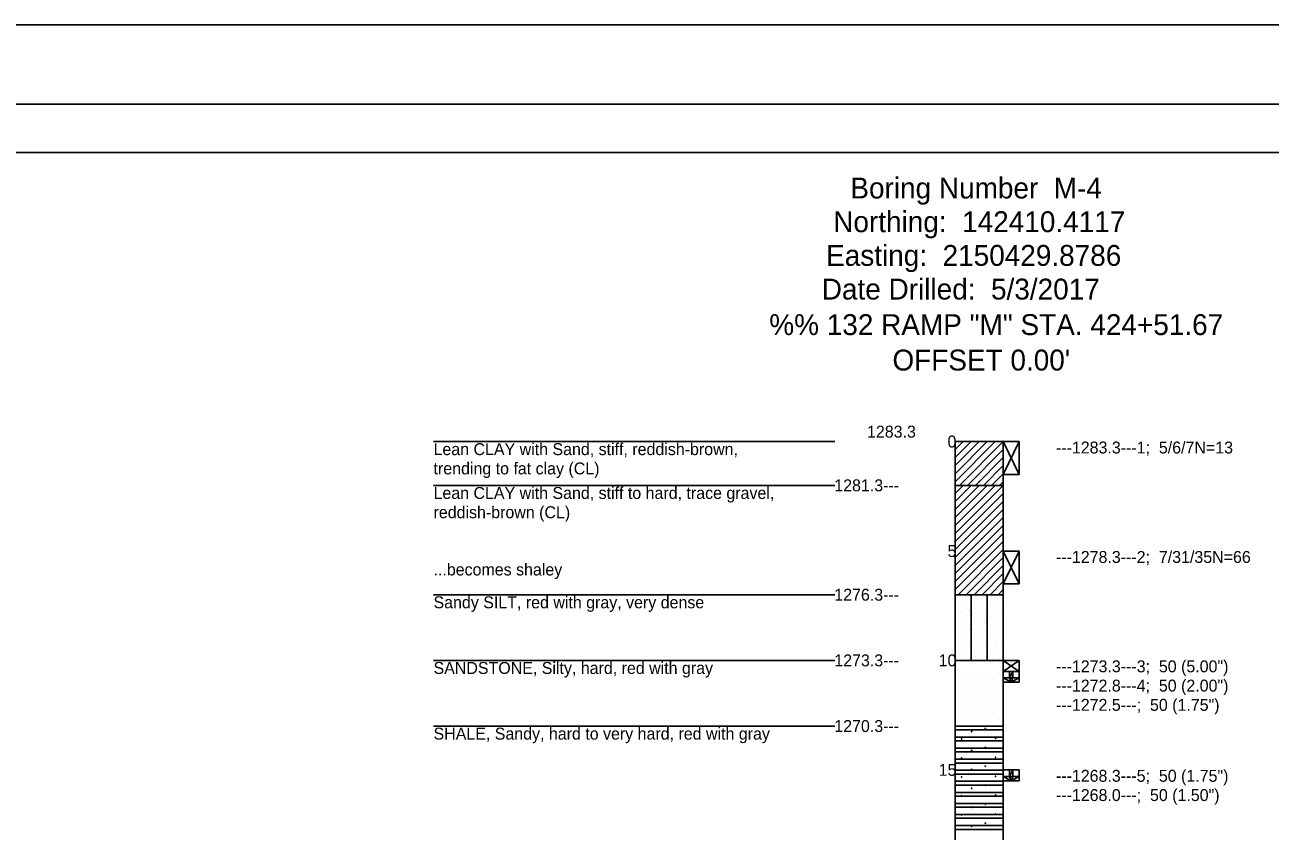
# Model space of a CAD drawing. Extents: x 2150161.5 to 2150203.1, y 143779.5 to 143868.5.
# Drawn here: x 2150182.3 to 2150195.23, y 143825.31 to 143833.69 of the extents above; entities that cross this region are included whole.
import ezdxf

# ---------------------------------------------------------------- set-up
doc = ezdxf.new("R2010")
doc.units = 0
for name, color, linetype in [('Default', 7, 'Continuous'), ('SHT_Plot_Shape_Full', 7, 'Continuous'), ('SHT_Plot_Shape_Half', 7, 'Continuous'), ('SHT_Sheet_Border', 7, 'Continuous')]:
    doc.layers.add(name, color=color, linetype=linetype)

# ---------------------------------------------------------------- blocks, each defined once
blk = doc.blocks.new('POINT_DISPLAY')
at = {"layer": 'Default'}
blk.add_line((0, 0), (0, 0), dxfattribs=at)

msp = doc.modelspace()

# ---------------------------------------------------------------- linework, layer by layer
at = {"layer": 'Default'}
for points in [[(2150186.544, 143829.36), (2150190.71, 143829.36)], [(2150191.96, 143829.276), (2150192.044, 143829.36)], [(2150191.96, 143829.193), (2150192.127, 143829.36)], [(2150191.96, 143829.11), (2150192.21, 143829.36)], [(2150191.96, 143829.026), (2150192.294, 143829.36)], [(2150191.96, 143828.943), (2150192.377, 143829.36)], [(2150191.96, 143829.36), (2150191.96, 143817.2)], [(2150191.96, 143829.36), (2150192.46, 143829.36)], [(2150192.006, 143828.905), (2150192.46, 143829.36)], [(2150192.089, 143828.905), (2150192.46, 143829.276)], [(2150192.46, 143829.36), (2150192.627, 143829.019)], [(2150192.46, 143829.019), (2150192.627, 143829.36)], [(2150192.46, 143829.36), (2150192.627, 143829.36)], [(2150192.46, 143829.36), (2150192.46, 143817.2)], [(2150192.627, 143829.019), (2150192.627, 143829.36)], [(2150192.173, 143828.905), (2150192.46, 143829.193)], [(2150192.256, 143828.905), (2150192.46, 143829.11)], [(2150192.339, 143828.905), (2150192.46, 143829.026)], [(2150192.46, 143829.019), (2150192.627, 143829.019)], [(2150186.544, 143828.905), (2150190.71, 143828.905)], [(2150191.96, 143828.905), (2150192.46, 143828.905)], [(2150191.96, 143828.822), (2150192.044, 143828.905)], [(2150191.96, 143828.738), (2150192.127, 143828.905)], [(2150191.96, 143828.655), (2150192.21, 143828.905)], [(2150191.96, 143828.572), (2150192.294, 143828.905)], [(2150191.96, 143828.488), (2150192.377, 143828.905)], [(2150191.96, 143828.405), (2150192.46, 143828.905)], [(2150192.423, 143828.905), (2150192.46, 143828.943)], [(2150191.96, 143828.322), (2150192.46, 143828.822)], [(2150191.96, 143828.238), (2150192.46, 143828.738)], [(2150191.96, 143828.155), (2150192.46, 143828.655)], [(2150191.96, 143828.072), (2150192.46, 143828.572)], [(2150191.96, 143827.988), (2150192.46, 143828.488)], [(2150191.96, 143827.905), (2150192.46, 143828.405)], [(2150191.96, 143827.822), (2150192.46, 143828.322)], [(2150191.991, 143827.769), (2150192.46, 143828.238)], [(2150192.074, 143827.769), (2150192.46, 143828.155)], [(2150192.46, 143828.223), (2150192.627, 143827.882)], [(2150192.46, 143827.882), (2150192.627, 143828.223)], [(2150192.46, 143828.223), (2150192.627, 143828.223)], [(2150192.627, 143827.882), (2150192.627, 143828.223)], [(2150192.157, 143827.769), (2150192.46, 143828.072)], [(2150192.241, 143827.769), (2150192.46, 143827.988)], [(2150192.324, 143827.769), (2150192.46, 143827.905)], [(2150192.46, 143827.882), (2150192.627, 143827.882)], [(2150186.544, 143827.769), (2150190.71, 143827.769)], [(2150191.96, 143827.769), (2150192.46, 143827.769)], [(2150192.127, 143827.087), (2150192.127, 143827.769)], [(2150192.294, 143827.087), (2150192.294, 143827.769)], [(2150192.407, 143827.769), (2150192.46, 143827.822)], [(2150186.544, 143827.087), (2150190.71, 143827.087)], [(2150191.96, 143827.087), (2150192.46, 143827.087)], [(2150192.46, 143827.087), (2150192.627, 143826.973)], [(2150192.46, 143826.973), (2150192.627, 143827.087)], [(2150192.46, 143827.087), (2150192.627, 143827.087)], [(2150192.627, 143826.973), (2150192.627, 143827.087)], [(2150192.46, 143826.973), (2150192.627, 143826.973)], [(2150192.46, 143826.973), (2150192.627, 143826.973)], [(2150192.627, 143826.86), (2150192.627, 143826.973)], [(2150192.46, 143826.86), (2150192.627, 143826.86)], [(2150186.544, 143826.405), (2150190.71, 143826.405)], [(2150191.96, 143826.405), (2150192.46, 143826.405)], [(2150191.96, 143826.405), (2150192.46, 143826.405)], [(2150191.96, 143826.366), (2150192.46, 143826.366)], [(2150192.135, 143826.349), (2150192.134, 143826.352), (2150192.131, 143826.352), (2150192.129, 143826.349), (2150192.131, 143826.346), (2150192.134, 143826.346), (2150192.135, 143826.349)], [(2150192.278, 143826.381), (2150192.276, 143826.384), (2150192.273, 143826.384), (2150192.272, 143826.381), (2150192.273, 143826.378), (2150192.276, 143826.378), (2150192.278, 143826.381)], [(2150191.96, 143826.29), (2150192.46, 143826.29)], [(2150191.96, 143826.251), (2150192.46, 143826.251)], [(2150191.96, 143826.175), (2150192.46, 143826.175)], [(2150192.031, 143826.27), (2150192.029, 143826.273), (2150192.026, 143826.273), (2150192.024, 143826.27), (2150192.026, 143826.267), (2150192.029, 143826.267), (2150192.031, 143826.27)], [(2150192.278, 143826.184), (2150192.276, 143826.187), (2150192.273, 143826.187), (2150192.272, 143826.184), (2150192.273, 143826.181), (2150192.276, 143826.181), (2150192.278, 143826.184)], [(2150192.384, 143826.277), (2150192.382, 143826.28), (2150192.379, 143826.28), (2150192.377, 143826.277), (2150192.379, 143826.274), (2150192.382, 143826.274), (2150192.384, 143826.277)], [(2150191.96, 143826.136), (2150192.46, 143826.136)], [(2150191.96, 143826.06), (2150192.46, 143826.06)], [(2150192.031, 143826.073), (2150192.029, 143826.076), (2150192.026, 143826.076), (2150192.024, 143826.073), (2150192.026, 143826.07), (2150192.029, 143826.07), (2150192.031, 143826.073)], [(2150192.135, 143826.152), (2150192.134, 143826.155), (2150192.131, 143826.155), (2150192.129, 143826.152), (2150192.131, 143826.149), (2150192.134, 143826.149), (2150192.135, 143826.152)], [(2150192.384, 143826.08), (2150192.382, 143826.083), (2150192.379, 143826.083), (2150192.377, 143826.08), (2150192.379, 143826.077), (2150192.382, 143826.077), (2150192.384, 143826.08)], [(2150191.96, 143826.021), (2150192.46, 143826.021)], [(2150191.96, 143825.946), (2150192.46, 143825.946)], [(2150192.135, 143825.955), (2150192.134, 143825.958), (2150192.131, 143825.958), (2150192.129, 143825.955), (2150192.131, 143825.953), (2150192.134, 143825.953), (2150192.135, 143825.955)], [(2150192.278, 143825.987), (2150192.276, 143825.99), (2150192.273, 143825.99), (2150192.272, 143825.987), (2150192.273, 143825.984), (2150192.276, 143825.984), (2150192.278, 143825.987)], [(2150192.46, 143825.95), (2150192.627, 143825.95)], [(2150192.627, 143825.837), (2150192.627, 143825.95)], [(2150191.96, 143825.906), (2150192.46, 143825.906)], [(2150191.96, 143825.831), (2150192.46, 143825.831)], [(2150191.96, 143825.791), (2150192.46, 143825.791)], [(2150192.031, 143825.876), (2150192.029, 143825.879), (2150192.026, 143825.879), (2150192.024, 143825.876), (2150192.026, 143825.874), (2150192.029, 143825.874), (2150192.031, 143825.876)], [(2150192.278, 143825.79), (2150192.276, 143825.793), (2150192.273, 143825.793), (2150192.272, 143825.79), (2150192.273, 143825.788), (2150192.276, 143825.788), (2150192.278, 143825.79)], [(2150192.384, 143825.883), (2150192.382, 143825.886), (2150192.379, 143825.886), (2150192.377, 143825.883), (2150192.379, 143825.88), (2150192.382, 143825.88), (2150192.384, 143825.883)], [(2150192.46, 143825.837), (2150192.627, 143825.837)], [(2150191.96, 143825.716), (2150192.46, 143825.716)], [(2150191.96, 143825.677), (2150192.46, 143825.677)], [(2150192.031, 143825.68), (2150192.029, 143825.682), (2150192.026, 143825.682), (2150192.024, 143825.68), (2150192.026, 143825.677), (2150192.029, 143825.677), (2150192.031, 143825.68)], [(2150192.135, 143825.759), (2150192.134, 143825.761), (2150192.131, 143825.761), (2150192.129, 143825.759), (2150192.131, 143825.756), (2150192.134, 143825.756), (2150192.135, 143825.759)], [(2150192.384, 143825.686), (2150192.382, 143825.689), (2150192.379, 143825.689), (2150192.377, 143825.686), (2150192.379, 143825.683), (2150192.382, 143825.683), (2150192.384, 143825.686)], [(2150191.96, 143825.601), (2150192.46, 143825.601)], [(2150191.96, 143825.562), (2150192.46, 143825.562)], [(2150192.135, 143825.562), (2150192.134, 143825.565), (2150192.131, 143825.565), (2150192.129, 143825.562), (2150192.131, 143825.559), (2150192.134, 143825.559), (2150192.135, 143825.562)], [(2150192.278, 143825.594), (2150192.276, 143825.596), (2150192.273, 143825.596), (2150192.272, 143825.594), (2150192.273, 143825.591), (2150192.276, 143825.591), (2150192.278, 143825.594)], [(2150191.96, 143825.486), (2150192.46, 143825.486)], [(2150191.96, 143825.447), (2150192.46, 143825.447)], [(2150192.031, 143825.483), (2150192.029, 143825.486), (2150192.026, 143825.486), (2150192.024, 143825.483), (2150192.026, 143825.48), (2150192.029, 143825.48), (2150192.031, 143825.483)], [(2150192.278, 143825.397), (2150192.276, 143825.4), (2150192.273, 143825.4), (2150192.272, 143825.397), (2150192.273, 143825.394), (2150192.276, 143825.394), (2150192.278, 143825.397)], [(2150192.384, 143825.489), (2150192.382, 143825.492), (2150192.379, 143825.492), (2150192.377, 143825.489), (2150192.379, 143825.486), (2150192.382, 143825.486), (2150192.384, 143825.489)], [(2150191.96, 143825.372), (2150192.46, 143825.372)], [(2150191.96, 143825.332), (2150192.46, 143825.332)], [(2150192.135, 143825.365), (2150192.134, 143825.368), (2150192.131, 143825.368), (2150192.129, 143825.365), (2150192.131, 143825.362), (2150192.134, 143825.362), (2150192.135, 143825.365)]]:
    msp.add_lwpolyline(points, dxfattribs=at)
for points in [[(2150192.527, 143826.905), (2150192.56, 143826.905), (2150192.56, 143826.973), (2150192.527, 143826.905)], [(2150192.527, 143826.905), (2150192.56, 143826.973), (2150192.527, 143826.973), (2150192.527, 143826.905)], [(2150192.527, 143826.905), (2150192.46, 143826.905), (2150192.544, 143826.86), (2150192.527, 143826.905)], [(2150192.527, 143826.905), (2150192.544, 143826.86), (2150192.56, 143826.905), (2150192.527, 143826.905)], [(2150192.544, 143826.86), (2150192.627, 143826.905), (2150192.56, 143826.905), (2150192.544, 143826.86)], [(2150192.527, 143825.882), (2150192.56, 143825.882), (2150192.56, 143825.95), (2150192.527, 143825.882)], [(2150192.527, 143825.882), (2150192.56, 143825.95), (2150192.527, 143825.95), (2150192.527, 143825.882)], [(2150192.527, 143825.882), (2150192.46, 143825.882), (2150192.544, 143825.837), (2150192.527, 143825.882)], [(2150192.527, 143825.882), (2150192.544, 143825.837), (2150192.56, 143825.882), (2150192.527, 143825.882)], [(2150192.544, 143825.837), (2150192.627, 143825.882), (2150192.56, 143825.882), (2150192.544, 143825.837)]]:
    msp.add_lwpolyline(points, close=True, dxfattribs=at)
at = {"layer": 'SHT_Plot_Shape_Full'}
msp.add_lwpolyline([(2150164.575, 143833.688), (2150200.575, 143833.688), (2150200.575, 143809.688), (2150164.575, 143809.688)], close=True, dxfattribs=at)
at = {"layer": 'SHT_Plot_Shape_Half'}
msp.add_lwpolyline([(2150166.212, 143832.863), (2150200.212, 143832.863), (2150200.212, 143810.863), (2150166.212, 143810.863)], close=True, dxfattribs=at)
at = {"layer": 'SHT_Sheet_Border'}
msp.add_lwpolyline([(2150199.662, 143811.363), (2150168.162, 143811.363), (2150168.162, 143832.363), (2150199.662, 143832.363)], close=True, dxfattribs=at)

# ---------------------------------------------------------------- block references
at = {"layer": 'Default', "xscale": 0.39369999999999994, "yscale": 0.3936999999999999}
for p in [(2150191.966, 143829.276), (2150192, 143829.343), (2150192.066, 143829.31), (2150192.166, 143829.343), (2150192.189, 143829.279), (2150192.266, 143829.31), (2150192.386, 143829.326), (2150192.433, 143829.276), (2150192, 143829.176), (2150192.033, 143829.243), (2150192.1, 143829.21), (2150192.233, 143829.243), (2150192.25, 143829.167), (2150192.333, 143829.243), (2150192.4, 143829.176), (2150191.966, 143829.043), (2150192.033, 143829.11), (2150192.1, 143829.076), (2150192.166, 143829.143), (2150192.185, 143829.066), (2150192.266, 143829.11), (2150192.384, 143829.091), (2150192.433, 143829.043), (2150192, 143828.888), (2150192.033, 143828.91), (2150192.066, 143829.01), (2150192.133, 143828.976), (2150192.166, 143828.888), (2150192.2, 143828.943), (2150192.236, 143828.996), (2150192.279, 143828.91), (2150192.3, 143829.01), (2150192.366, 143828.976), (2150192.4, 143828.91), (2150191.966, 143828.822), (2150192.033, 143828.788), (2150192.066, 143828.855), (2150192.189, 143828.825), (2150192.233, 143828.788), (2150192.266, 143828.855), (2150192.333, 143828.788), (2150192.386, 143828.872), (2150192.433, 143828.822), (2150192, 143828.722), (2150192.033, 143828.655), (2150192.1, 143828.755), (2150192.166, 143828.688), (2150192.25, 143828.713), (2150192.266, 143828.655), (2150192.384, 143828.637), (2150192.4, 143828.722), (2150191.966, 143828.588), (2150192.066, 143828.555), (2150192.1, 143828.622), (2150192.133, 143828.522), (2150192.185, 143828.611), (2150192.236, 143828.541), (2150192.3, 143828.555), (2150192.366, 143828.522), (2150192.433, 143828.588), (2150191.966, 143828.388), (2150192.033, 143828.455), (2150192.166, 143828.422), (2150192.2, 143828.488), (2150192.279, 143828.455), (2150192.333, 143828.388), (2150192.4, 143828.455), (2150192, 143828.322), (2150192.066, 143828.355), (2150192.2, 143828.288), (2150192.233, 143828.355), (2150192.3, 143828.255), (2150192.4, 143828.322), (2150191.966, 143828.155), (2150192, 143828.222), (2150192.033, 143828.122), (2150192.066, 143828.188), (2150192.166, 143828.222), (2150192.189, 143828.158), (2150192.233, 143828.122), (2150192.266, 143828.188), (2150192.333, 143828.122), (2150192.386, 143828.205), (2150192.433, 143828.155), (2150192, 143828.055), (2150192.033, 143827.988), (2150192.1, 143828.088), (2150192.166, 143828.022), (2150192.25, 143828.046), (2150192.266, 143827.988), (2150192.4, 143828.055), (2150191.966, 143827.922), (2150192.066, 143827.888), (2150192.1, 143827.955), (2150192.133, 143827.855), (2150192.185, 143827.944), (2150192.236, 143827.875), (2150192.3, 143827.888), (2150192.366, 143827.855), (2150192.384, 143827.97), (2150192.433, 143827.922), (2150191.99, 143827.756), (2150192.033, 143827.788), (2150192.04, 143827.731), (2150192.115, 143827.756), (2150192.19, 143827.731), (2150192.2, 143827.822), (2150192.279, 143827.788), (2150192.28, 143827.744), (2150192.365, 143827.756), (2150192.4, 143827.788), (2150192.44, 143827.731), (2150191.965, 143827.706), (2150191.99, 143827.631), (2150192.015, 143827.681), (2150192.065, 143827.656), (2150192.115, 143827.606), (2150192.132, 143827.708), (2150192.165, 143827.681), (2150192.177, 143827.624), (2150192.24, 143827.681), (2150192.29, 143827.631), (2150192.315, 143827.706), (2150192.347, 143827.603), (2150192.365, 143827.656), (2150192.407, 143827.599), (2150192.415, 143827.681), (2150192.456, 143827.606), (2150191.965, 143827.531), (2150192.015, 143827.581), (2150192.04, 143827.506), (2150192.065, 143827.556), (2150192.09, 143827.481), (2150192.129, 143827.548), (2150192.167, 143827.496), (2150192.19, 143827.581), (2150192.215, 143827.506), (2150192.265, 143827.481), (2150192.278, 143827.567), (2150192.315, 143827.531), (2150192.365, 143827.556), (2150192.415, 143827.506), (2150192.44, 143827.556), (2150191.965, 143827.381), (2150192.015, 143827.431), (2150192.04, 143827.356), (2150192.115, 143827.406), (2150192.14, 143827.456), (2150192.165, 143827.356), (2150192.199, 143827.431), (2150192.24, 143827.381), (2150192.29, 143827.431), (2150192.34, 143827.456), (2150192.341, 143827.356), (2150192.365, 143827.406), (2150192.415, 143827.356), (2150192.433, 143827.437), (2150191.965, 143827.206), (2150191.99, 143827.331), (2150191.99, 143827.256), (2150192.04, 143827.231), (2150192.115, 143827.256), (2150192.132, 143827.208), (2150192.14, 143827.306), (2150192.19, 143827.231), (2150192.215, 143827.281), (2150192.28, 143827.244), (2150192.29, 143827.331), (2150192.315, 143827.206), (2150192.365, 143827.256), (2150192.39, 143827.281), (2150192.44, 143827.231), (2150192.459, 143827.306), (2150191.99, 143827.131), (2150192.015, 143827.181), (2150192.065, 143827.156), (2150192.115, 143827.106), (2150192.165, 143827.181), (2150192.177, 143827.124), (2150192.24, 143827.181), (2150192.29, 143827.131), (2150192.347, 143827.103), (2150192.365, 143827.156), (2150192.407, 143827.099), (2150192.415, 143827.181), (2150192.456, 143827.106), (2150192.032, 143827.06), (2150192.032, 143826.961), (2150192.13, 143827.06), (2150192.13, 143826.961), (2150192.228, 143827.06), (2150192.228, 143826.961), (2150192.327, 143827.06), (2150192.327, 143826.961), (2150192.425, 143827.06), (2150192.425, 143826.961), (2150192.032, 143826.863), (2150192.13, 143826.863), (2150192.228, 143826.863), (2150192.327, 143826.863), (2150192.425, 143826.863), (2150192.032, 143826.764), (2150192.13, 143826.764), (2150192.228, 143826.764), (2150192.327, 143826.764), (2150192.425, 143826.764), (2150192.032, 143826.666), (2150192.032, 143826.567), (2150192.13, 143826.666), (2150192.13, 143826.567), (2150192.228, 143826.666), (2150192.228, 143826.567), (2150192.327, 143826.666), (2150192.327, 143826.567), (2150192.425, 143826.666), (2150192.425, 143826.567), (2150192.032, 143826.469), (2150192.13, 143826.469), (2150192.228, 143826.469), (2150192.327, 143826.469), (2150192.425, 143826.469)]:
    msp.add_blockref('POINT_DISPLAY', p, dxfattribs=at)

# ---------------------------------------------------------------- texts
at = {"layer": 'Default'}
for s, height, p in [('Boring Number  M-4', 0.217, (2150190.873, 143831.885)), ('Northing:  142410.4117', 0.217, (2150190.695, 143831.535)), ('Easting:  2150429.8786', 0.217, (2150190.621, 143831.185)), ('Date Drilled:  5/3/2017', 0.217, (2150190.576, 143830.835)), ('%% 132 RAMP "M" STA. 424+51.67', 0.217, (2150190.031, 143830.466)), ("OFFSET 0.00'", 0.217, (2150191.31, 143830.098)), ('1283.3', 0.124, (2150191.046, 143829.401)), ('0', 0.124, (2150191.882, 143829.298)), ('Lean CLAY with Sand, stiff, reddish-brown,', 0.124, (2150186.544, 143829.219)), ('---1283.3---1;  5/6/7N=13', 0.124, (2150193.008, 143829.236)), ('trending to fat clay (CL)', 0.124, (2150186.544, 143829.019)), ('Lean CLAY with Sand, stiff to hard, trace gravel,', 0.124, (2150186.544, 143828.764)), ('1281.3---', 0.124, (2150190.706, 143828.843)), ('reddish-brown (CL)', 0.124, (2150186.544, 143828.564)), ('5', 0.124, (2150191.882, 143828.161)), ('---1278.3---2;  7/31/35N=66', 0.124, (2150193.008, 143828.099)), ('...becomes shaley', 0.124, (2150186.544, 143827.969)), ('Sandy SILT, red with gray, very dense', 0.124, (2150186.544, 143827.628)), ('1276.3---', 0.124, (2150190.706, 143827.707)), ('SANDSTONE, Silty, hard, red with gray', 0.124, (2150186.544, 143826.946)), ('1273.3---', 0.124, (2150190.706, 143827.025)), ('10', 0.124, (2150191.79, 143827.025)), ('---1273.3---3;  50 (5.00")', 0.124, (2150193.008, 143826.963)), ('---1272.8---4;  50 (2.00")', 0.124, (2150193.008, 143826.763)), ('---1272.5---;  50 (1.75")', 0.124, (2150193.008, 143826.563)), ('1270.3---', 0.124, (2150190.706, 143826.343)), ('SHALE, Sandy, hard to very hard, red with gray', 0.124, (2150186.544, 143826.264)), ('15', 0.124, (2150191.79, 143825.888)), ('---1268.3---5;  50 (1.75")', 0.124, (2150193.008, 143825.826)), ('---1268.0---;  50 (1.50")', 0.124, (2150193.008, 143825.626))]:
    msp.add_text(s, height=height, dxfattribs=at).set_placement(p)

doc.saveas('drawing.dxf')
